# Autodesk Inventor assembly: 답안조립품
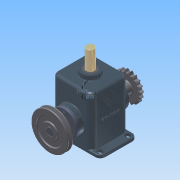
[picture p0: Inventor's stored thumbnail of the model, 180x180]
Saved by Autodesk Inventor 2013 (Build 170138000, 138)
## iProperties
Created: 2015-03
Part Number: 답안조립품
Document SubType Name: Assembly
Designer: Administrator
Mass: 8579.28 g
Surface Area: 4386.42 cm^2
Volume: 1982.54 cm^3
Density: 4.32742 g/cm^3
Author: Administrator
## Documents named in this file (15)
- C:\Documents and Settings\Administrator\바탕 화면\350305V1032\답안조립품.iam
- C:\Documents and Settings\Administrator\바탕 화면\350305V1032\본체.ipt
- C:\Documents and Settings\Administrator\바탕 화면\350305V1032\베어링 6205.ipt
- C:\Documents and Settings\Administrator\바탕 화면\350305V1032\커버.ipt
- C:\Documents and Settings\Administrator\바탕 화면\350305V1032\M4x0.5.ipt
- C:\Documents and Settings\Administrator\바탕 화면\350305V1032\편심축.ipt
- C:\Documents and Settings\Administrator\바탕 화면\350305V1032\멈춤링.ipt
- C:\Documents and Settings\Administrator\바탕 화면\350305V1032\오일실.ipt
- C:\Documents and Settings\Administrator\바탕 화면\350305V1032\체인 스프로킷.ipt
- C:\Documents and Settings\Administrator\바탕 화면\350305V1032\키 8x8.ipt
- C:\Documents and Settings\Administrator\바탕 화면\350305V1032\V-벨트풀리.ipt
- C:\Documents and Settings\Administrator\바탕 화면\350305V1032\멈춤나사 M5x0.5.ipt
- C:\Documents and Settings\Administrator\바탕 화면\350305V1032\부시.ipt
- C:\Documents and Settings\Administrator\바탕 화면\350305V1032\슬라이드.ipt
- C:\Documents and Settings\Administrator\바탕 화면\350305V1032\7-가변스프링.ipt
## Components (9 placed, 4 different names)
1. 5-체인 스프로킷:1 — 플러쉬:1, 각도:3
2. V-벨트풀리:1 — 플러쉬:2, 각도:4
3. 7-가변스프링:1 — 각도:7
4. M4x0.5:1
5. M4x0.5:3
6. M4x0.5:4
7. M4x0.5:2
8. M4x0.5:5
9. M4x0.5:6
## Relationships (5: Angle 3, Flush 2)
- 플러쉬:1 [Flush]: 5-체인 스프로킷:1
- 각도:3 [Angle]: 5-체인 스프로킷:1
- 플러쉬:2 [Flush]: V-벨트풀리:1
- 각도:4 [Angle]: V-벨트풀리:1
- 각도:7 [Angle]: 7-가변스프링:1
